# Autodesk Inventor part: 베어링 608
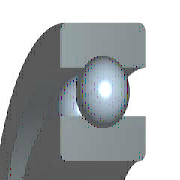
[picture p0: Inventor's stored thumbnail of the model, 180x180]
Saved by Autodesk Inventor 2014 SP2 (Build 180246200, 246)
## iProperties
IsCustomPart: 1
Company: 한국ATC센터
Created: 2014-07
Part Number: 베어링 608
Material: 강, 연강
Description: 깊은 그루브 볼 베어링
Document SubType Name: Modeling
Standard: KS B 2023
Designer: KYOUNG IL JANG
Standards Organization: KS
Language: ko-KR
Size Designation: 608 - 8 x 22 x 7
Categories: <MemberInstance><Categories><Category DisplayName="샤프트 부품" InternalName="7f7aeb1f-a693-4053-b835-cee3144e0d98" Mnemonic="SHFT"><Category DisplayName="베어링" Inter
Density: 1 g/cm^3
Appearance: 강철
Author: KYOUNG IL JANG
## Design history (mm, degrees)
sketch "스케치" dims "d0" = 3.64 (= -0.26 x WD + 0.26 x BD)
  geometry: L1 (1.68, 7.5)-(5.32, 7.5); L2 (3.5, 7.5)-(3.5, 5.68); L3 (3.5, 7.5)-(3.5, 9.32); L4 (2.148, 6.282)-(0, 6.282); L5 (0, 4)-(7, 4); L6 (2.148, 8.718)-(0, 8.718); L7 (0, 11)-(7, 11); L8 (7, 4)-(7, 6.282); L9 (4.852, 6.282)-(7, 6.282); L10 (4.852, 8.718)-(7, 8.718); L11 (7, 11)-(7, 8.718); L12 (-1.4, 0)-(8.4, 0) reference; L13 (0, -0.3)-(0, 5.3) reference
  constraints: 22 end point, 4 point on line, 2 collinear, 2 perpendicular, 2 symmetric about line, 1 midpoint, 1 parallel, 14 other
  dimensions: "d9" = 8 diameter of L5 L12 (= WD); "d11" = 22 diameter of L7 L12 (= BD); "d12" = 7 distance between parallel lines of L8 L13 (= KB); "d13" = 12.564 diameter of L9 L12 (= 0.326 x BD + 0.674 x WD)
revolve "본체" stored, may be unused: angle "d6" = 90 deg
revolve "볼" stored, may be unused: angle "d7" = 90 deg
pattern_circular "IDS_ARRAYBALL[SIMPL:T]" dims angle "d3" = 360 deg
body "Solid1"
fillet "모깎기1" dims "d1" = 0.3 (= KRS)
other parameters: "WD" = 8 [user parameter; used in 5 equation terms], "BD" = 22 [user parameter; used in 5 equation terms], "KB" = 7 [user parameter; used in 1 equation term], "KRS" = 0.3 [user parameter; used in 1 equation term], "d4" = 0, "d5" = 0, "d8" = 0, "d14" = 0, "d15" = 0, "BBA" = 0 [user parameter], "BC0" = 1370000 [user parameter], "BC" = 3250000 [user parameter], "BR" = 11 (= 0.5 x BD) [user parameter], "WR" = 4 (= 0.5 x WD) [user parameter]
